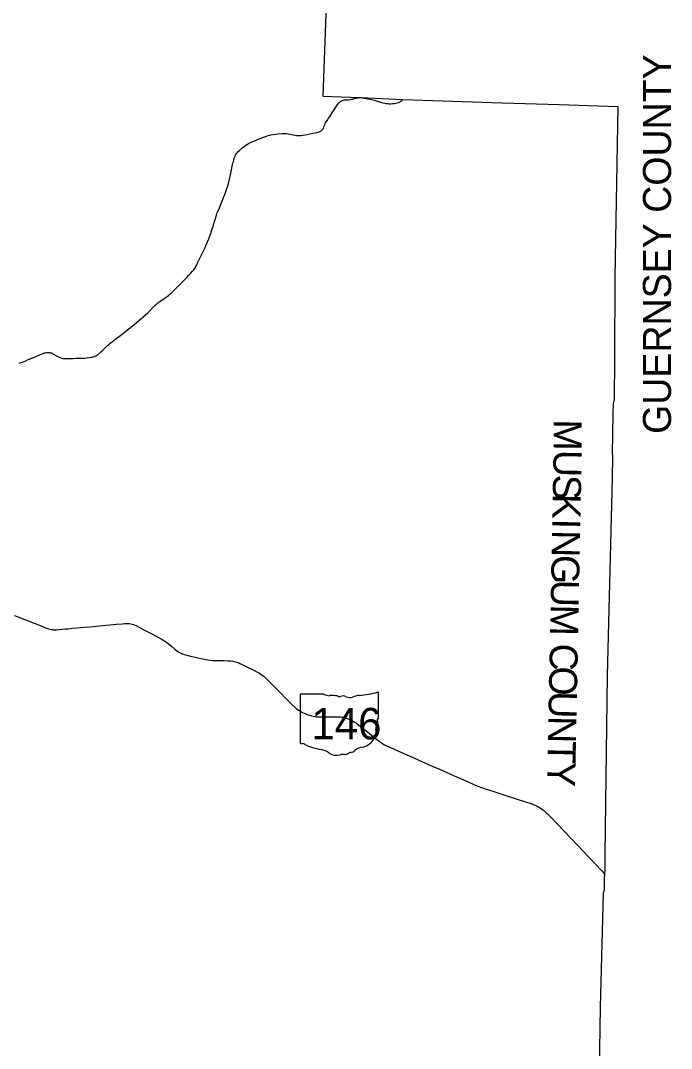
# Model space of a CAD drawing. Extents: x 2015843 to 2287843, y 623733 to 799733.
# Drawn here: x 2189000 to 2212197, y 665553 to 702171 of the extents above; entities that cross this region are included whole.
import ezdxf

# ---------------------------------------------------------------- set-up
doc = ezdxf.new("R2010")
doc.units = 0
for name, color, linetype in [('GM_X_County', 7, 'Continuous'), ('GM_X_County_Text', 7, 'Continuous'), ('GM_X_State_Location', 7, 'Continuous'), ('GM_X_State_Route', 7, 'Continuous'), ('GM_X_State_Shield', 7, 'Continuous')]:
    doc.layers.add(name, color=color, linetype=linetype)

msp = doc.modelspace()

# ---------------------------------------------------------------- linework, layer by layer
at = {"layer": 'GM_X_County'}
msp.add_lwpolyline([(2200352, 715403), (2199774, 699473), (2201089, 699432), (2201116, 699431), (2201134, 699430), (2202626, 699355), (2206162, 699242), (2208195, 699179), (2210280, 699112), (2210180, 693025), (2210170, 690133), (2210151, 688640), (2210142, 688621), (2210136, 688604), (2210132, 688585), (2210129, 688569), (2210127, 688554), (2210125, 688537), (2210121, 688494), (2210119, 688456), (2210115, 688374), (2210113, 688325), (2210111, 688276), (2210105, 688097), (2210105, 688073), (2210104, 688049), (2210104, 688032), (2210104, 687966), (2210103, 687884), (2210100, 687721), (2210097, 687522), (2210094, 687247), (2210091, 687121), (2210089, 687031), (2210086, 686899), (2210089, 686771), (2210091, 686640), (2210092, 686493), (2210092, 686411), (2210092, 686298), (2210089, 686216), (2210085, 685941), (2210084, 685916), (2210083, 685902), (2210082, 685889), (2210079, 685870), (2209901, 678842), (2209827, 672479), (2209818, 671863), (2209815, 671768), (2209806, 671695), (2209803, 671676), (2209799, 671617), (2209797, 671558), (2209797, 671513), (2209798, 671434), (2209800, 671342), (2209798, 671257), (2209795, 671202), (2209790, 671166), (2209785, 671141), (2209779, 671122), (2209765, 671089), (2209653, 667025), (2209624, 664772)], dxfattribs=at)
at = {"layer": 'GM_X_State_Route'}
for points in [[(2196811, 697558), (2196847, 697592), (2196898, 697633), (2196964, 697683), (2197031, 697730), (2197086, 697766), (2197129, 697791), (2197172, 697814), (2197247, 697848), (2197369, 697898), (2197505, 697953), (2197689, 698025), (2197766, 698053), (2197828, 698074), (2197876, 698088), (2197924, 698099), (2197988, 698111), (2198086, 698123), (2198167, 698132), (2198314, 698148), (2198363, 698152), (2198412, 698152), (2198462, 698150), (2198495, 698146), (2198543, 698137), (2198655, 698110), (2198719, 698096), (2198783, 698084), (2198831, 698077), (2198864, 698074), (2198896, 698072), (2198945, 698072), (2198993, 698077), (2199057, 698089), (2199138, 698105), (2199203, 698117), (2199358, 698146), (2199483, 698171), (2199564, 698188), (2199611, 698198), (2199642, 698208), (2199671, 698221), (2199699, 698236), (2199713, 698245), (2199738, 698266), (2199749, 698277), (2199760, 698289), (2199770, 698302), (2199779, 698315), (2199794, 698343), (2199813, 698388), (2199832, 698433), (2199851, 698479), (2199872, 698523), (2199897, 698566), (2199933, 698621), (2199979, 698689), (2200034, 698770), (2200122, 698908), (2200148, 698950), (2200236, 699088), (2200281, 699157), (2200309, 699197), (2200341, 699235), (2200364, 699259), (2200389, 699281), (2200402, 699291), (2200430, 699309), (2200445, 699316), (2200475, 699328), (2200507, 699338), (2200540, 699344), (2200556, 699346), (2200605, 699348), (2200655, 699349), (2200704, 699352), (2200752, 699357), (2200800, 699365), (2200847, 699376), (2200901, 699391), (2200942, 699402), (2200962, 699407)], [(2200962, 699407), (2200977, 699412), (2201023, 699420)], [(2201023, 699420), (2201063, 699427), (2201090, 699429), (2201117, 699428), (2201135, 699427), (2201162, 699424), (2201186, 699421), (2201248, 699411), (2201297, 699401)], [(2201297, 699401), (2201369, 699388), (2201455, 699370), (2201551, 699347), (2201615, 699329), (2201709, 699299), (2201787, 699274), (2201866, 699252), (2201914, 699241), (2201978, 699228), (2202027, 699220), (2202092, 699213), (2202141, 699210), (2202190, 699210), (2202256, 699214), (2202321, 699220), (2202370, 699228), (2202418, 699238), (2202465, 699251), (2202495, 699262), (2202505, 699268), (2202524, 699277), (2202551, 699295), (2202604, 699333), (2202627, 699353)], [(2191499, 690176), (2191539, 690184), (2191587, 690195), (2191607, 690201), (2191618, 690204), (2191648, 690215), (2191678, 690229), (2191720, 690253), (2191761, 690280), (2191800, 690310), (2191849, 690353), (2191909, 690408), (2192015, 690511), (2192097, 690591), (2192145, 690636), (2192195, 690678), (2192273, 690739), (2192391, 690827), (2192574, 690965), (2192742, 691097), (2193047, 691346), (2193286, 691545), (2193448, 691683), (2193520, 691750), (2193590, 691819), (2193726, 691961), (2193785, 692018), (2193847, 692073), (2193898, 692114), (2193964, 692163), (2194153, 692293), (2194220, 692340), (2194273, 692379), (2194323, 692421), (2194395, 692487), (2194478, 692567), (2194571, 692659), (2194721, 692810), (2194829, 692920), (2194920, 693012), (2194991, 693091), (2195064, 693169), (2195127, 693238), (2195170, 693288), (2195200, 693327), (2195227, 693367), (2195250, 693410), (2195277, 693469), (2195317, 693559), (2195576, 694090), (2195618, 694178), (2195664, 694283), (2195708, 694389), (2195749, 694496), (2195782, 694589), (2195822, 694713), (2195852, 694807), (2195876, 694887), (2195904, 694979), (2195937, 695089), (2195979, 695234), (2196000, 695292), (2196030, 695368), (2196088, 695504), (2196152, 695655), (2196202, 695776), (2196212, 695802), (2196238, 695868), (2196292, 696005), (2196332, 696112), (2196357, 696190), (2196385, 696284), (2196417, 696412), (2196489, 696731), (2196571, 697099), (2196573, 697104), (2196595, 697195), (2196614, 697258), (2196630, 697305), (2196650, 697350), (2196674, 697394), (2196701, 697435), (2196732, 697474), (2196764, 697512), (2196799, 697547), (2196811, 697558)], [(2188956, 689969), (2189161, 690042), (2189251, 690079), (2189401, 690144), (2189492, 690182), (2189567, 690214), (2189733, 690285), (2189810, 690315), (2189857, 690331), (2189889, 690339), (2189938, 690347), (2189971, 690349), (2190004, 690349), (2190037, 690346), (2190070, 690339), (2190101, 690328), (2190132, 690315), (2190175, 690291), (2190260, 690241), (2190330, 690199), (2190373, 690177), (2190403, 690163), (2190433, 690153), (2190464, 690144), (2190512, 690135), (2190561, 690129), (2190610, 690126), (2190675, 690126), (2190878, 690135), (2190983, 690139), (2191115, 690139), (2191226, 690142), (2191296, 690148), (2191378, 690156), (2191459, 690168), (2191499, 690176)], [(2188788, 680976), (2189490, 680700), (2189734, 680604), (2189917, 680531), (2189994, 680504), (2190041, 680490), (2190089, 680479), (2190137, 680472), (2190169, 680469), (2190218, 680468), (2190283, 680471), (2190496, 680488), (2190594, 680497), (2190691, 680507), (2190838, 680521), (2191001, 680536), (2191263, 680560), (2191475, 680578), (2191818, 680610), (2192422, 680664), (2192618, 680682), (2192717, 680688), (2192782, 680691), (2192832, 680690), (2192881, 680686), (2192930, 680678), (2192979, 680668), (2193026, 680654), (2193072, 680637), (2193118, 680616), (2193393, 680471), (2193540, 680398), (2193656, 680337), (2193830, 680245), (2193901, 680205), (2194012, 680140), (2194110, 680080), (2194178, 680035), (2194258, 679977), (2194323, 679927), (2194386, 679875), (2194509, 679768), (2194560, 679727), (2194600, 679699), (2194642, 679674), (2194699, 679643), (2194758, 679616), (2194804, 679598), (2194865, 679577), (2194928, 679560), (2195056, 679530), (2195279, 679479), (2195487, 679432), (2195599, 679409), (2195680, 679395), (2195745, 679386), (2195826, 679379), (2195890, 679377), (2195941, 679375), (2196236, 679369), (2196400, 679363), (2196498, 679357), (2196564, 679351), (2196613, 679343), (2196661, 679331), (2196708, 679317), (2196754, 679299), (2196814, 679272), (2196903, 679229), (2197035, 679164), (2197315, 679027), (2197418, 678975), (2197475, 678942), (2197558, 678890), (2197612, 678852), (2197665, 678813), (2197703, 678781), (2197751, 678736), (2198027, 678456), (2198200, 678280), (2198511, 677966), (2198638, 677837), (2198708, 677769), (2198722, 677756), (2198777, 677706), (2198827, 677665), (2198880, 677626), (2198934, 677589), (2198990, 677555), (2199047, 677523), (2199106, 677495), (2199166, 677470), (2199243, 677442), (2199305, 677422), (2199368, 677405), (2199432, 677391), (2199513, 677377), (2199561, 677371), (2199610, 677367), (2199692, 677364), (2199987, 677365), (2200051, 677367), (2200215, 677369), (2200264, 677369), (2200316, 677368), (2200363, 677366), (2200405, 677364), (2200451, 677358), (2200495, 677352), (2200532, 677344), (2200573, 677333), (2200605, 677324), (2200667, 677300), (2200729, 677276), (2200774, 677255), (2200832, 677224), (2200889, 677191), (2200930, 677165), (2200970, 677137), (2201048, 677078), (2201202, 676956), (2201318, 676864), (2201420, 676782), (2201638, 676608), (2201781, 676497), (2201848, 676450), (2201916, 676406), (2201973, 676373), (2202045, 676335), (2202134, 676293), (2202358, 676192), (2203034, 675894), (2203694, 675603), (2203904, 675509), (2204429, 675278), (2204925, 675060), (2205180, 674948), (2205301, 674898), (2205424, 674852), (2205563, 674803), (2205828, 674716), (2206296, 674566), (2206999, 674338), (2207186, 674276), (2207224, 674262), (2207266, 674247), (2207305, 674231), (2207343, 674215), (2207384, 674196), (2207442, 674165), (2207499, 674132), (2207554, 674096), (2207608, 674058), (2207634, 674038), (2207659, 674017), (2207722, 673963), (2207781, 673907), (2207873, 673813), (2208381, 673277), (2208845, 672790), (2209252, 672362), (2209715, 671875), (2209786, 671801), (2209816, 671766)]]:
    msp.add_lwpolyline(points, dxfattribs=at)
at = {"layer": 'GM_X_State_Shield'}
for p, q in [((2199807, 678175), (2198986, 678175)), ((2201760, 677327), (2201760, 678217)), ((2198959, 678145), (2198959, 676444)), ((2201760, 677327), (2201760, 677327))]:
    msp.add_line(p, q, dxfattribs=at)
for centre, major_axis, start_param, end_param in [((2198991, 678149), (32.5, 0), 1.712693, 3.28349), ((2200002, 678372), (315, 0), 4.042523, 4.731795), ((2200762, 680494), (2971, 0), 4.814394, 5.042369), ((2201729, 678221), (31.2, 0), 6.141152, 7.989035), ((2200106, 677220), (1130, 0), 1.404758, 1.657858), ((2200363, 678158), (90.8, 0), 3.836095, 5.185415), ((2200496, 677961), (189, 0), 0.950623, 2.079405), ((2200740, 678231), (227, 0), 4.081561, 5.145723), ((2201141, 677655), (598, 0), 1.699011, 2.107814), ((2201872, 676955), (211, 0), 2.387724, 3.262537), ((2201753, 677262), (48.3, 0), 1.883978, 3.671073), ((2201446, 677149), (290, 0), 5.934695, 6.695948), ((2201727, 677324), (33.4, 0), 5.05454, 6.418171), ((2200929, 676841), (743, 0), 5.101752, 6.440018), ((2198991, 676441), (32.7, 0), 3.00124, 4.508301), ((2198996, 676615), (250, 0), 4.665946, 4.897461), ((2199047, 676346), (90.1, 0), 0.519207, 1.627899), ((2200185, 677875), (2146, 0), 4.195997, 4.488961), ((2199545, 675680), (671, 0), 0.823519, 1.323587), ((2200271, 676338), (426, 0), 4.026481, 4.996735), ((2200517, 675750), (350, 0), 1.495662, 1.94098), ((2200548, 676210), (227, 0), 4.691044, 5.507374), ((2200754, 676046), (63.9, 0), 1.147584, 2.315152), ((2200726, 676279), (240, 0), 4.937069, 5.64225), ((2201242, 675967), (407, 0), 1.647645, 2.488434)]:
    msp.add_ellipse(centre, major_axis=major_axis, ratio=0.8, start_param=start_param, end_param=end_param, dxfattribs=at)

# ---------------------------------------------------------------- texts
at = {"layer": 'GM_X_County_Text'}
for s, rotation, p in [('GUERNSEY COUNTY', 90, (2212182, 687445)), ('M', 269.5558, (2208002, 687966)), ('U', 269.1779, (2207994, 686881)), ('S', 269.0462, (2207981, 685997)), ('K', 268.9125, (2207970, 685320)), ('I', 268.8718, (2207953, 684436)), ('N', 268.856, (2207945, 684027)), ('G', 268.8538, (2207927, 683143)), ('U', 268.8516, (2207910, 682258)), ('M', 268.853, (2207892, 681374)), ('C', 268.8539, (2207864, 679984)), ('O', 268.8516, (2207848, 679170)), ('U', 268.8536, (2207830, 678286)), ('N', 268.8538, (2207812, 677402)), ('T', 268.8531, (2207795, 676518)), ('Y', 268.8516, (2207780, 675770))]:
    msp.add_text(s, height=1000, rotation=rotation, dxfattribs=at).set_placement(p)
at = {"layer": 'GM_X_State_Location'}
msp.add_text('146', height=1, rotation=0, dxfattribs=at).set_placement((2200226, 677143))
for s in ['s', 'r']:
    msp.add_text(s, height=1, dxfattribs=at).set_placement((2200579, 677215))
at = {"layer": 'GM_X_State_Shield'}
msp.add_text('146', height=1120.7, dxfattribs=at).set_placement((2199362, 676564))

doc.saveas('drawing.dxf')
